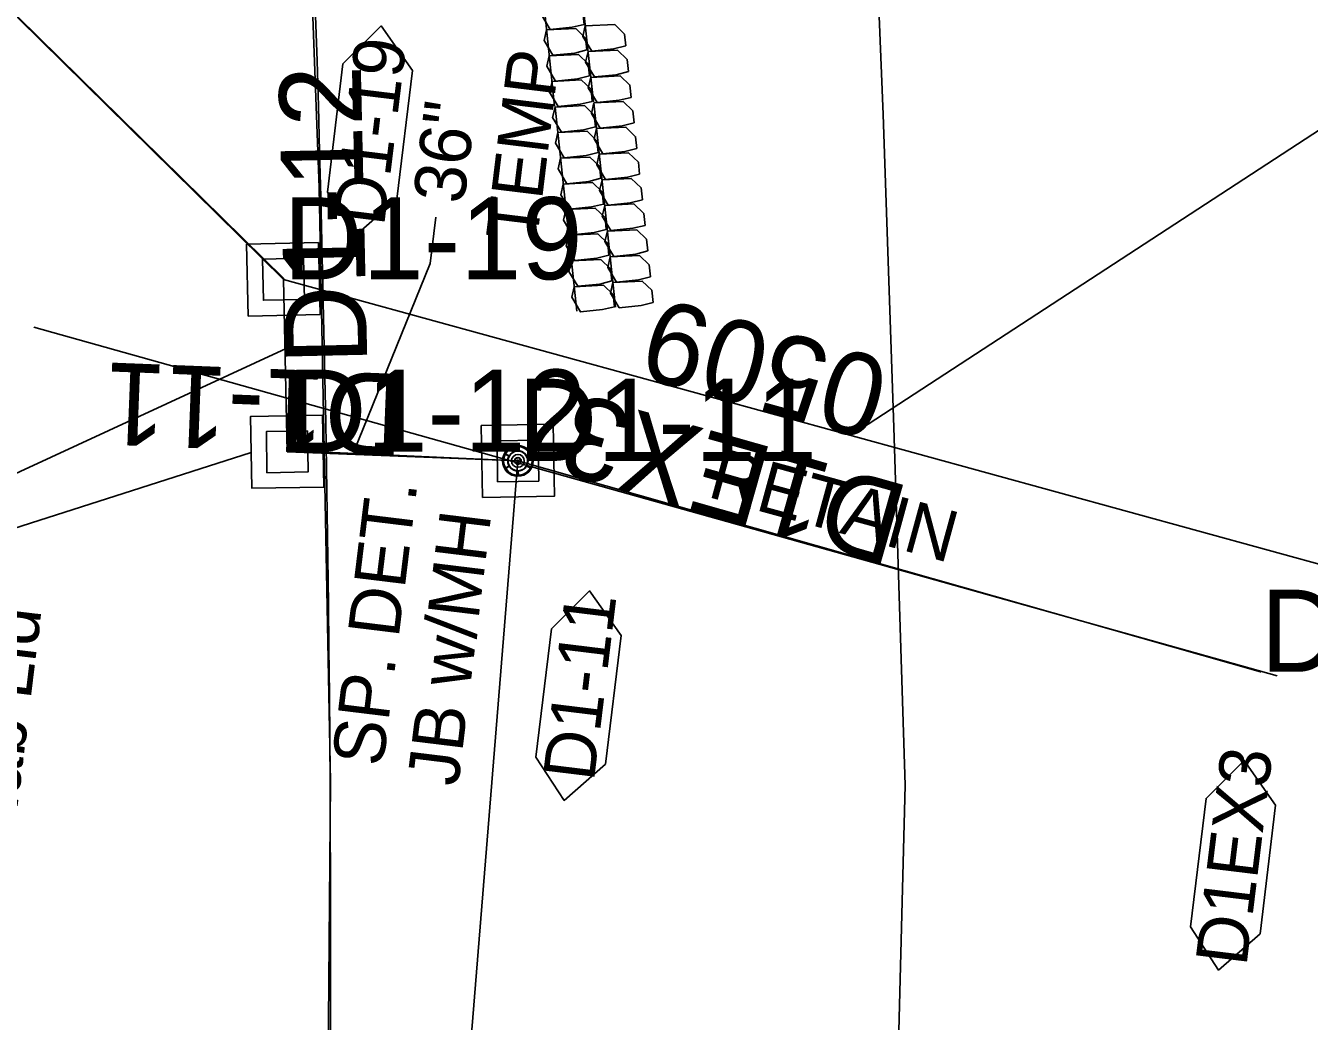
# Model space of a CAD drawing. Extents: x 465700 to 483515, y 488970 to 507540.
# Drawn here: x 481328 to 481453, y 491354.2 to 491451.2 of the extents above; entities that cross this region are included whole.
import ezdxf

# ---------------------------------------------------------------- set-up
doc = ezdxf.new("R2010")
doc.units = 0
for name, color, linetype in [('Default', 7, 'Continuous'), ('Exist Plan Preparation Watershed Blue', 7, 'Continuous'), ('Prop Drainage Structure Box Number Symbol CELL', 7, 'Continuous'), ('Prop Drainage Structure Junction Box with Manhole CELL', 7, 'Continuous'), ('Prop Drainage Structure Junction Box with Manhole Label', 7, 'Continuous'), ('Prop Drainage Structure Junction Box with Slab Lid CELL', 7, 'Continuous'), ('Prop Drainage Structure Junction Box with Slab Lid Label', 7, 'Continuous'), ('Prop Drainage Structure Pipe Collar Label', 7, 'Continuous'), ('Prop Drainage Structure Pipe RCP 15in Class III', 7, 'Continuous'), ('Prop Drainage Structure Pipe RCP 36in Class III', 7, 'Continuous'), ('Prop Drainage Structure Pipe RCP 48in Class III', 7, 'Continuous'), ('Prop Drainage Structure Pipe Stub Out CELL', 7, 'Continuous'), ('Prop Drainage Structure Plot Symbol 20 Scale', 7, 'Continuous'), ('Prop Drainage Structure Plot Symbol 50 Scale', 7, 'Continuous'), ('Prop Erosion Embankment Toe Protection CELL', 7, 'Continuous'), ('Prop NEU Channel Block Detail Label', 7, 'Continuous'), ('Scratch_Level_4', 7, 'Continuous'), ('Scratch_Level_8', 7, 'Continuous')]:
    doc.layers.add(name, color=color, linetype=linetype)

msp = doc.modelspace()

# ---------------------------------------------------------------- linework, layer by layer
at = {"layer": 'Default'}
msp.add_arc((478448.2, 491360.26), 2909.5, 356.95228, 8.055, dxfattribs=at)
at = {"layer": 'Exist Plan Preparation Watershed Blue'}
for points in [[(482127.99, 491863.91), (481786.78, 491759.9), (481568.07, 491531.08), (481568.07, 491531.08), (481568.07, 491531.08), (481568.07, 491531.08), (481568.07, 491531.08), (481489.54, 491524.26), (481441, 491522.17), (481407.45, 491514.97), (481410.05, 491479.29), (481411.52, 491442.54), (481412.58, 491412.05), (481413.67, 491377.22), (481412.27, 491323.04), (481409.74, 491273.14), (481403.82, 491209.49), (481400.35, 491179.93)], [(481351.25, 491164.11), (481355.63, 491237.92), (481357.02, 491295.88), (481357.71, 491377.55), (481356.61, 491435.42), (481354.34, 491495.85), (481349.13, 491584.55), (481341.19, 491673.05), (481328.95, 491769.45), (481331.36, 491785.24), (481338.28, 491786.26), (481358.32, 491790.73), (481372.6, 491727.76), (481383.56, 491677.38), (481390.7, 491636.27), (481400.08, 491578.77), (481407.45, 491514.97), (481410.05, 491479.29), (481411.52, 491442.54), (481412.58, 491412.05), (481413.67, 491377.22), (481412.27, 491323.04), (481409.74, 491273.14), (481400.35, 491179.93)]]:
    msp.add_lwpolyline(points, dxfattribs=at)
at = {"layer": 'Prop Drainage Structure Box Number Symbol CELL'}
for points in [[(481357.39, 491434.97), (481358.91, 491447.49), (481362.62, 491451.17), (481365.69, 491446.82), (481364.17, 491434.31), (481360.13, 491430.77), (481357.39, 491434.97)], [(481377.71, 491379.96), (481379.24, 491392.47), (481382.94, 491396.15), (481386.02, 491391.8), (481384.49, 491379.29), (481380.46, 491375.75), (481377.71, 491379.96)], [(481441.46, 491363.43), (481442.98, 491375.94), (481446.69, 491379.62), (481449.76, 491375.27), (481448.24, 491362.76), (481444.2, 491359.22), (481441.46, 491363.43)]]:
    msp.add_lwpolyline(points, dxfattribs=at)
at = {"layer": 'Prop Drainage Structure Junction Box with Manhole CELL'}
for p, q in [((481375.93, 491410.19), (481375.93, 491410.19)), ((481374.57, 491408.78), (481374.57, 491408.78)), ((481375.95, 491408.81), (481375.95, 491408.81)), ((481377.34, 491408.83), (481377.34, 491408.83)), ((481375.97, 491407.42), (481375.97, 491407.42))]:
    msp.add_line(p, q, dxfattribs=at)
for points in [[(481374.73, 491409.46), (481375.08, 491409.27), (481375.1, 491409.31), (481374.75, 491409.5)], [(481375.95, 491410.19), (481375.96, 491409.8), (481375.91, 491409.8), (481375.91, 491410.19)], [(481377.15, 491409.5), (481376.81, 491409.3), (481376.79, 491409.33), (481377.13, 491409.54)], [(481374.77, 491408.08), (481375.11, 491408.28), (481375.09, 491408.32), (481374.75, 491408.11)], [(481377.15, 491408.12), (481376.81, 491408.31), (481376.83, 491408.35), (481377.17, 491408.15), (481377.17, 491408.15)], [(481375.95, 491407.42), (481375.95, 491407.82), (481375.99, 491407.82), (481376, 491407.42)]]:
    msp.add_lwpolyline(points, dxfattribs=at)
for radius in [1.39, 0.99, 0.953, 0.625, 0.333, 0.292, 0.0834, 0.0417]:
    msp.add_circle((481375.95, 491408.81), radius, dxfattribs=at)
at = {"layer": 'Prop Drainage Structure Junction Box with Manhole Label'}
msp.add_lwpolyline([(481359.93, 491409.62), (481367.41, 491428.04), (481367.96, 491432.55)], dxfattribs=at)
at = {"layer": 'Prop Drainage Structure Junction Box with Slab Lid CELL'}
for p, q in [((481353.06, 491428.49), (481353.06, 491428.49)), ((481351.11, 491426.45), (481351.11, 491426.45)), ((481353.11, 491426.49), (481353.11, 491426.49)), ((481355.11, 491426.54), (481355.11, 491426.54)), ((481353.16, 491424.49), (481353.16, 491424.49)), ((481353.45, 491411.7), (481353.45, 491411.7)), ((481351.48, 491409.66), (481351.48, 491409.66)), ((481353.48, 491409.7), (481353.48, 491409.7)), ((481355.48, 491409.73), (481355.48, 491409.73)), ((481353.51, 491407.7), (481353.51, 491407.7))]:
    msp.add_line(p, q, dxfattribs=at)
for points in [[(481351.06, 491428.45), (481355.06, 491428.54), (481355.15, 491424.54), (481351.16, 491424.45)], [(481351.45, 491411.66), (481355.45, 491411.73), (481355.51, 491407.73), (481351.51, 491407.66)]]:
    msp.add_lwpolyline(points, close=True, dxfattribs=at)
at = {"layer": 'Prop Drainage Structure Pipe RCP 15in Class III'}
msp.add_line((481349.75, 491085.88), (481375.95, 491408.81), dxfattribs=at)
at = {"layer": 'Prop Drainage Structure Pipe RCP 36in Class III'}
for p, q in [((481353.48, 491409.7), (481353.11, 491426.49)), ((481375.95, 491408.81), (481353.61, 491409.81))]:
    msp.add_line(p, q, dxfattribs=at)
at = {"layer": 'Prop Drainage Structure Pipe RCP 48in Class III'}
msp.add_line((481353.17, 491426.53), (481291.33, 491487.38), dxfattribs=at)
at = {"layer": 'Prop Drainage Structure Pipe Stub Out CELL'}
msp.add_line((481448.29, 491388.27), (481448.29, 491388.27), dxfattribs=at)
msp.add_line((481448.29, 491388.27), (481448.29, 491388.27), dxfattribs=at)
msp.add_lwpolyline([(481448.27, 491388.27), (481448.29, 491388.29), (481448.31, 491388.27), (481448.29, 491388.26), (481448.27, 491388.27)], dxfattribs=at)
at = {"layer": 'Prop Drainage Structure Plot Symbol 20 Scale'}
for points in [[(481355.06, 491428.54), (481355.15, 491424.54), (481351.16, 491424.45), (481351.06, 491428.45)], [(481355.45, 491411.73), (481355.51, 491407.73), (481351.51, 491407.66), (481351.45, 491411.66)], [(481373.98, 491406.77), (481373.92, 491410.77), (481377.92, 491410.84), (481377.98, 491406.84)]]:
    msp.add_lwpolyline(points, close=True, dxfattribs=at)
msp.add_circle((481375.95, 491408.81), 1.5, dxfattribs=at)
at = {"layer": 'Prop Drainage Structure Plot Symbol 50 Scale'}
for points in [[(481356.53, 491430.07), (481356.69, 491423.07), (481349.69, 491422.91), (481349.53, 491429.91)], [(481356.92, 491413.25), (481357.04, 491406.26), (481350.04, 491406.14), (481349.92, 491413.14)], [(481372.51, 491405.25), (481372.39, 491412.25), (481379.39, 491412.37), (481379.51, 491405.37)]]:
    msp.add_lwpolyline(points, close=True, dxfattribs=at)
msp.add_circle((481375.95, 491408.81), 1.5, dxfattribs=at)
at = {"layer": 'Prop Erosion Embankment Toe Protection CELL'}
for p, q in [((481377.42, 491463.26), (481379.53, 491443.37)), ((481381.2, 491463.66), (481383.31, 491443.77)), ((481379.58, 491443.27), (481381.68, 491423.38)), ((481383.36, 491443.67), (481385.46, 491423.78))]:
    msp.add_line(p, q, dxfattribs=at)
for points in [[(481382.41, 491451.32), (481381.23, 491451.04), (481379.09, 491450.82), (481378.24, 491452.24), (481378.48, 491453.27), (481381.33, 491453.42), (481382.29, 491452.49), (481382.41, 491451.32)], [(481382.67, 491448.83), (481381.5, 491448.53), (481379.36, 491448.31), (481378.5, 491449.75), (481378.75, 491450.78), (481381.6, 491450.91), (481382.55, 491449.98), (481382.67, 491448.83)], [(481386.45, 491449.23), (481385.28, 491448.93), (481383.14, 491448.71), (481382.28, 491450.15), (481382.52, 491451.18), (481385.38, 491451.31), (481386.33, 491450.38), (481386.45, 491449.23)], [(481382.94, 491446.32), (481381.76, 491446.02), (481379.63, 491445.8), (481378.77, 491447.24), (481379.01, 491448.27), (481381.86, 491448.4), (481382.81, 491447.49), (481382.94, 491446.32)], [(481386.72, 491446.72), (481385.54, 491446.42), (481383.4, 491446.2), (481382.55, 491447.64), (481382.79, 491448.67), (481385.64, 491448.8), (481386.59, 491447.89), (481386.72, 491446.72)], [(481383.2, 491443.81), (481382.03, 491443.54), (481379.89, 491443.31), (481379.03, 491444.73), (481379.28, 491445.76), (481382.13, 491445.91), (481383.08, 491445), (481383.2, 491443.81)], [(481386.98, 491444.21), (481385.81, 491443.94), (481383.67, 491443.71), (481382.81, 491445.13), (481383.06, 491446.16), (481385.91, 491446.31), (481386.86, 491445.4), (481386.98, 491444.21)], [(481383.5, 491441.33), (481382.33, 491441.05), (481380.19, 491440.82), (481379.33, 491442.24), (481379.58, 491443.27), (481382.43, 491443.42), (481383.38, 491442.49), (481383.5, 491441.33)], [(481387.28, 491441.73), (481386.1, 491441.45), (481383.97, 491441.22), (481383.11, 491442.64), (481383.36, 491443.67), (481386.21, 491443.82), (481387.16, 491442.89), (481387.28, 491441.73)], [(481383.77, 491438.84), (481382.59, 491438.54), (481380.45, 491438.31), (481379.6, 491439.76), (481379.84, 491440.79), (481382.69, 491440.91), (481383.65, 491439.98), (481383.77, 491438.84)], [(481387.55, 491439.24), (481386.37, 491438.94), (481384.23, 491438.71), (481383.38, 491440.16), (481383.62, 491441.19), (481386.47, 491441.31), (481387.42, 491440.38), (481387.55, 491439.24)], [(481384.03, 491436.33), (481382.86, 491436.03), (481380.72, 491435.8), (481379.86, 491437.24), (481380.11, 491438.28), (481382.96, 491438.4), (481383.91, 491437.5), (481384.03, 491436.33)], [(481387.81, 491436.73), (481386.64, 491436.43), (481384.5, 491436.2), (481383.64, 491437.64), (481383.88, 491438.68), (481386.74, 491438.8), (481387.69, 491437.9), (481387.81, 491436.73)], [(481384.3, 491433.82), (481383.12, 491433.54), (481380.98, 491433.32), (481380.13, 491434.73), (481380.37, 491435.76), (481383.22, 491435.92), (481384.17, 491435.01), (481384.3, 491433.82)], [(481388.08, 491434.22), (481386.9, 491433.94), (481384.76, 491433.72), (481383.91, 491435.13), (481384.15, 491436.17), (481387, 491436.32), (481387.95, 491435.41), (481388.08, 491434.22)], [(481384.56, 491431.33), (481383.38, 491431.06), (481381.25, 491430.83), (481380.39, 491432.25), (481380.63, 491433.28), (481383.48, 491433.43), (481384.44, 491432.5), (481384.56, 491431.33)], [(481388.34, 491431.73), (481387.16, 491431.46), (481385.02, 491431.23), (481384.17, 491432.65), (481384.41, 491433.68), (481387.26, 491433.83), (481388.22, 491432.9), (481388.34, 491431.73)], [(481384.82, 491428.85), (481383.65, 491428.55), (481381.51, 491428.32), (481380.66, 491429.76), (481380.9, 491430.79), (481383.75, 491430.92), (481384.7, 491429.99), (481384.82, 491428.85)], [(481388.6, 491429.25), (481387.43, 491428.95), (481385.29, 491428.72), (481384.43, 491430.16), (481384.68, 491431.19), (481387.53, 491431.32), (481388.48, 491430.39), (481388.6, 491429.25)], [(481385.09, 491426.33), (481383.92, 491426.03), (481381.78, 491425.81), (481380.92, 491427.25), (481381.16, 491428.28), (481384.02, 491428.41), (481384.97, 491427.5), (481385.09, 491426.33)], [(481388.87, 491426.73), (481387.69, 491426.43), (481385.56, 491426.21), (481384.7, 491427.65), (481384.94, 491428.68), (481387.8, 491428.81), (481388.75, 491427.9), (481388.87, 491426.73)], [(481385.36, 491423.82), (481384.18, 491423.55), (481382.04, 491423.32), (481381.19, 491424.74), (481381.43, 491425.77), (481384.28, 491425.92), (481385.23, 491425.02), (481385.36, 491423.82)], [(481389.14, 491424.22), (481387.96, 491423.95), (481385.82, 491423.72), (481384.97, 491425.14), (481385.21, 491426.17), (481388.06, 491426.32), (481389.01, 491425.42), (481389.14, 491424.22)]]:
    msp.add_lwpolyline(points, dxfattribs=at)
at = {"layer": 'Prop NEU Channel Block Detail Label'}
for points in [[(481409.33, 491411.91), (481513.98, 491480.18), (481515.3, 491491.02)], [(481353.37, 491419.75), (481295.92, 491393.21), (481295.34, 491388.84)], [(481349.98, 491409.64), (481322.66, 491400.89), (481322.09, 491396.52)]]:
    msp.add_lwpolyline(points, dxfattribs=at)
at = {"layer": 'Scratch_Level_4'}
msp.add_line((481449.9, 491387.89), (481328.8, 491421.83), dxfattribs=at)
at = {"layer": 'Scratch_Level_8'}
for p, q in [((481353.11, 491426.49), (481291.33, 491487.38)), ((481353.48, 491409.7), (481353.11, 491426.49)), ((481467.7, 491394.98), (481353.11, 491426.49)), ((481375.95, 491408.81), (481353.48, 491409.7)), ((481349.75, 491085.88), (481375.95, 491408.81)), ((481448.29, 491388.27), (481375.95, 491408.81))]:
    msp.add_line(p, q, dxfattribs=at)

# ---------------------------------------------------------------- texts
at = {"layer": 'Prop Drainage Structure Box Number Symbol CELL'}
for s, p in [('D1-19', (481362.91, 491431.58)), ('D1-11', (481383.35, 491377.51)), ('D1EX3', (481446.91, 491359.51))]:
    msp.add_text(s, height=5, rotation=83.0394, dxfattribs=at).set_placement(p)
at = {"layer": 'Prop Drainage Structure Junction Box with Manhole Label'}
for s, p in [('TEMP', (481377.8, 491430.08)), ('36"', (481370.69, 491433.74)), ('SP. DET.', (481362.8, 491378.94)), ('JB w/MH', (481370.12, 491377.04))]:
    msp.add_text(s, height=5, rotation=83.0365, dxfattribs=at).set_placement(p)
at = {"layer": 'Prop Drainage Structure Junction Box with Slab Lid Label'}
msp.add_text('JB w/Slab Lid', height=5, rotation=83.0423, dxfattribs=at).set_placement((481324.65, 491354.11))
at = {"layer": 'Prop Drainage Structure Pipe Collar Label'}
msp.add_text('RETAIN', height=5, rotation=344.7008, dxfattribs=at).set_placement((481394.29, 491405.34))
at = {"layer": 'Prop Drainage Structure Pipe Stub Out CELL'}
msp.add_text('SO', height=0.0104, rotation=0.3571, dxfattribs=at).set_placement((481448.28, 491388.27))
at = {"layer": 'Scratch_Level_8'}
for s, rotation, p in [('D1-12', 91.262, (481361.29, 491418.27)), ('0509', 164.6246, (481412.53, 491418.45)), ('D1-11', 177.7373, (481365.03, 491417.25)), ('D1EX3', 164.1514, (481414.31, 491406.24))]:
    msp.add_text(s, height=8, rotation=rotation, dxfattribs=at).set_placement(p)
for s, p in [('D1-19', (481353.11, 491426.49)), ('D1-12', (481353.48, 491409.7)), ('D1-11', (481375.95, 491408.81)), ('D1EX3', (481448.29, 491388.27))]:
    msp.add_text(s, height=8, dxfattribs=at).set_placement(p)

doc.saveas('drawing.dxf')
